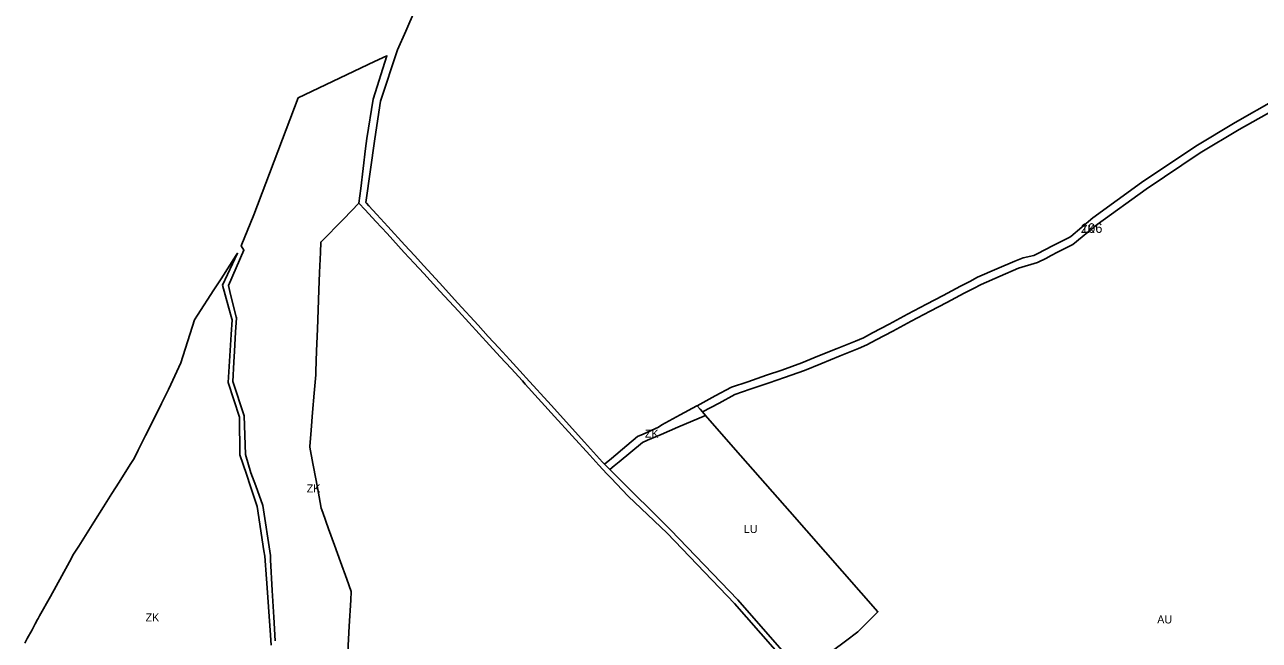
# Model space of a CAD drawing. Extents: x -537068 to -534056, y -1176840 to -1172401.
# Drawn here: x -536897 to -536126, y -1173545 to -1173160 of the extents above; entities that cross this region are included whole.
import ezdxf

# ---------------------------------------------------------------- set-up
doc = ezdxf.new("R2010")
doc.units = 0
for name, color, linetype in [('90710013', 7, 'Continuous'), ('90710023', 7, 'Continuous'), ('90750013', 7, 'Continuous'), ('90770013', 7, 'Continuous'), ('ID_navrh', 7, 'Continuous')]:
    doc.layers.add(name, color=color, linetype=linetype)

msp = doc.modelspace()

# ---------------------------------------------------------------- linework, layer by layer
at = {"layer": '90710013'}
for points in [[(-536740.8, -1173544.87), (-536741.62, -1173530.03), (-536742.54, -1173513.34), (-536743.58, -1173494.26), (-536743.73, -1173491.55), (-536748.44, -1173460.44), (-536752.87, -1173448.15), (-536755.82, -1173439.97), (-536759.21, -1173428.41), (-536759.86, -1173410.37), (-536760.07, -1173404.43), (-536767.21, -1173383.01), (-536766.5, -1173370.87), (-536766.1, -1173363.95), (-536765.41, -1173352.16), (-536764.89, -1173343.17), (-536765.07, -1173342.46), (-536766.85, -1173335.32), (-536769.02, -1173326.62), (-536769.92, -1173323), (-536760.29, -1173300.9), (-536761.91, -1173298.23), (-536754.11, -1173278.82), (-536726.26, -1173205.78), (-536678.67, -1173183.17), (-536670.93, -1173179.49), (-536679.48, -1173206.58), (-536683.5, -1173231.19), (-536684.26, -1173237.49), (-536687.27, -1173262.34), (-536688.39, -1173271.56), (-536697.92, -1173281.27), (-536712.23, -1173295.85), (-536712.48, -1173302.36), (-536712.95, -1173314.83), (-536713.37, -1173325.78), (-536713.85, -1173338.23), (-536714.31, -1173350.16), (-536714.83, -1173363.76), (-536715.32, -1173376.77), (-536715.4, -1173378.79), (-536716.34, -1173390.11), (-536717.35, -1173402.33), (-536718.26, -1173413.33), (-536719.1, -1173423.47), (-536719, -1173424.01), (-536717.13, -1173434.13), (-536715.17, -1173444.76), (-536713.3, -1173454.89), (-536712, -1173461.94), (-536710.97, -1173464.79), (-536707.33, -1173474.88), (-536703.66, -1173485.04), (-536699.85, -1173495.61), (-536695.94, -1173506.43), (-536693.21, -1173513.98), (-536693.52, -1173519.44), (-536694.43, -1173535.65), (-536695.35, -1173551.97)], [(-536897.15, -1173546.32), (-536895.96, -1173544.15), (-536895.72, -1173543.73), (-536895.52, -1173543.35), (-536892.58, -1173538.02), (-536890.52, -1173534.27), (-536889.05, -1173531.62), (-536888.66, -1173530.9), (-536887.8, -1173529.34), (-536881.06, -1173517.1), (-536873.99, -1173504.27), (-536869.22, -1173495.62), (-536866.57, -1173490.8), (-536863.34, -1173485.69), (-536859.16, -1173479.05), (-536853.98, -1173470.84), (-536847.94, -1173461.26), (-536842.65, -1173452.86), (-536838.18, -1173445.78), (-536832.27, -1173436.41), (-536830.84, -1173434.15), (-536828.87, -1173431.02), (-536826.22, -1173425.75), (-536821.63, -1173416.6), (-536816.78, -1173406.94), (-536811.63, -1173396.67), (-536807.24, -1173387.92), (-536805.86, -1173384.88), (-536799.66, -1173371.28), (-536791.11, -1173344.5), (-536789.23, -1173341.58), (-536778.96, -1173325.66), (-536774.53, -1173318.78), (-536765.04, -1173304.06), (-536764.23, -1173302.81), (-536773.59, -1173322.71), (-536771.89, -1173328.86), (-536769.61, -1173337.09), (-536767.72, -1173343.88), (-536767.58, -1173344.39), (-536768.19, -1173353.64), (-536768.85, -1173363.54), (-536770.17, -1173383.46), (-536762.97, -1173405.24), (-536762.75, -1173428.76), (-536758.67, -1173440.8), (-536756.08, -1173448.57), (-536755.51, -1173450.29), (-536751.91, -1173461.06), (-536747.73, -1173488.68), (-536747.24, -1173491.91), (-536746.21, -1173506.04), (-536744.94, -1173523.42), (-536744.91, -1173523.88), (-536743.87, -1173538.18), (-536743.18, -1173547.58)]]:
    msp.add_lwpolyline(points, dxfattribs=at)
msp.add_lwpolyline([(-536531.67, -1173437.87), (-536535.02, -1173434.53), (-536530.74, -1173430.93), (-536521.07, -1173422.8), (-536514.36, -1173417.16), (-536511, -1173415.71), (-536501.3, -1173411.52), (-536499.14, -1173410.01), (-536487.8, -1173403.75), (-536477.34, -1173398.13), (-536477.22, -1173398.07), (-536475.27, -1173400.29), (-536473.84, -1173401.92), (-536471.93, -1173404.1), (-536489.19, -1173411.48), (-536499.62, -1173415.94), (-536508.14, -1173419.59), (-536511.38, -1173420.98), (-536525.93, -1173433.09), (-536528.92, -1173435.58)], close=True, dxfattribs=at)
at = {"layer": '90710023'}
msp.add_lwpolyline([(-536113.11, -1173211.09), (-536138.71, -1173225.54), (-536163.03, -1173240.21), (-536196.76, -1173262.83), (-536227.35, -1173284.86), (-536242.63, -1173297.35), (-536251.72, -1173302.02), (-536256.57, -1173304.51), (-536259.11, -1173305.81), (-536264.58, -1173308.62), (-536276.53, -1173312.23), (-536287.98, -1173317.17), (-536299.84, -1173322.28), (-536304.64, -1173324.81), (-536310.37, -1173327.83), (-536315.87, -1173330.73), (-536321.29, -1173333.59), (-536331.65, -1173339.06), (-536343.44, -1173345.34), (-536355.02, -1173351.51), (-536365.31, -1173356.99), (-536371.16, -1173360.1), (-536376.47, -1173362.27), (-536387.87, -1173366.92), (-536399.85, -1173371.81), (-536410.04, -1173375.97), (-536422.65, -1173380.48), (-536432.27, -1173383.77), (-536443.98, -1173387.77), (-536453.72, -1173391.1), (-536463.51, -1173396.36), (-536473.84, -1173401.92), (-536475.27, -1173400.29), (-536477.22, -1173398.07), (-536465.88, -1173391.96), (-536455.73, -1173386.5), (-536445.6, -1173383.04), (-536433.89, -1173379.04), (-536424.3, -1173375.76), (-536411.83, -1173371.3), (-536401.74, -1173367.18), (-536389.76, -1173362.29), (-536378.36, -1173357.64), (-536373.28, -1173355.57), (-536367.66, -1173352.58), (-536357.37, -1173347.1), (-536345.79, -1173340.93), (-536333.99, -1173334.64), (-536323.62, -1173329.17), (-536318.2, -1173326.31), (-536312.7, -1173323.41), (-536306.97, -1173320.39), (-536302, -1173317.77), (-536289.96, -1173312.58), (-536278.74, -1173307.74), (-536273.57, -1173305.71), (-536266.86, -1173304.17), (-536263.18, -1173302.28), (-536261.39, -1173301.36), (-536258.85, -1173300.06), (-536256.07, -1173298.63), (-536254, -1173297.57), (-536244.91, -1173292.9), (-536243.78, -1173292.32), (-536230.04, -1173280.63), (-536199.61, -1173258.72), (-536165.72, -1173235.99), (-536141.23, -1173221.22), (-536115.5, -1173206.7)], dxfattribs=at)
at = {"layer": '90750013'}
for points in [[(-536115.5, -1173206.7), (-536141.23, -1173221.22), (-536165.72, -1173235.99), (-536199.61, -1173258.72), (-536230.04, -1173280.63), (-536243.78, -1173292.32), (-536244.91, -1173292.9), (-536254, -1173297.57), (-536256.07, -1173298.63), (-536258.85, -1173300.06), (-536261.39, -1173301.36), (-536263.18, -1173302.28), (-536266.86, -1173304.17), (-536273.57, -1173305.71), (-536278.74, -1173307.74), (-536289.96, -1173312.58), (-536302, -1173317.77), (-536306.97, -1173320.39), (-536312.7, -1173323.41), (-536318.2, -1173326.31), (-536323.62, -1173329.17), (-536333.99, -1173334.64), (-536345.79, -1173340.93), (-536357.37, -1173347.1), (-536367.66, -1173352.58), (-536373.28, -1173355.57), (-536378.36, -1173357.64), (-536389.76, -1173362.29), (-536401.74, -1173367.18), (-536411.83, -1173371.3), (-536424.3, -1173375.76), (-536433.89, -1173379.04), (-536445.6, -1173383.04), (-536455.73, -1173386.5), (-536465.88, -1173391.96), (-536477.22, -1173398.07), (-536477.34, -1173398.13), (-536487.8, -1173403.75), (-536499.14, -1173410.01), (-536501.3, -1173411.52), (-536511, -1173415.71), (-536514.36, -1173417.16), (-536521.07, -1173422.8), (-536530.74, -1173430.93), (-536535.02, -1173434.53), (-536536.29, -1173433.26), (-536547.63, -1173420.74), (-536568.41, -1173397.79), (-536584.04, -1173380.53), (-536585.84, -1173378.56), (-536594.23, -1173369.39), (-536600.99, -1173361.99), (-536607.64, -1173354.72), (-536614, -1173347.76), (-536626.56, -1173334.03), (-536638.15, -1173321.36), (-536647.89, -1173310.71), (-536653.74, -1173304.32), (-536659.71, -1173297.8), (-536670.35, -1173286.17), (-536677.16, -1173278.73), (-536682.24, -1173273.17), (-536683.71, -1173271.57), (-536684.19, -1173271.04), (-536678.39, -1173231.46), (-536674.84, -1173207.79), (-536664.26, -1173175.78), (-536659.19, -1173164.25), (-536653.2, -1173150.64)], [(-536384.64, -1173545.08), (-536376.87, -1173539.13), (-536376.51, -1173538.77), (-536364.3, -1173526.67), (-536419.21, -1173464.14), (-536453.14, -1173425.5), (-536471.93, -1173404.1), (-536473.84, -1173401.92), (-536463.51, -1173396.36), (-536453.72, -1173391.1), (-536443.98, -1173387.77), (-536432.27, -1173383.77), (-536422.65, -1173380.48), (-536410.04, -1173375.97), (-536399.85, -1173371.81), (-536387.87, -1173366.92), (-536376.47, -1173362.27), (-536371.16, -1173360.1), (-536365.31, -1173356.99), (-536355.02, -1173351.51), (-536343.44, -1173345.34), (-536331.65, -1173339.06), (-536321.29, -1173333.59), (-536315.87, -1173330.73), (-536310.37, -1173327.83), (-536304.64, -1173324.81), (-536299.84, -1173322.28), (-536287.98, -1173317.17), (-536276.53, -1173312.23), (-536264.58, -1173308.62), (-536259.11, -1173305.81), (-536256.57, -1173304.51), (-536251.72, -1173302.02), (-536242.63, -1173297.35), (-536227.35, -1173284.86), (-536196.76, -1173262.83), (-536163.03, -1173240.21), (-536138.71, -1173225.54), (-536113.11, -1173211.09)], [(-536695.35, -1173551.97), (-536694.43, -1173535.65), (-536693.52, -1173519.44), (-536693.21, -1173513.98), (-536695.94, -1173506.43), (-536699.85, -1173495.61), (-536703.66, -1173485.04), (-536707.33, -1173474.88), (-536710.97, -1173464.79), (-536712, -1173461.94), (-536713.3, -1173454.89), (-536715.17, -1173444.76), (-536717.13, -1173434.13), (-536719, -1173424.01), (-536719.1, -1173423.47), (-536718.26, -1173413.33), (-536717.35, -1173402.33), (-536716.34, -1173390.11), (-536715.4, -1173378.79), (-536715.32, -1173376.77), (-536714.83, -1173363.76), (-536714.31, -1173350.16), (-536713.85, -1173338.23), (-536713.37, -1173325.78), (-536712.95, -1173314.83), (-536712.48, -1173302.36), (-536712.23, -1173295.85), (-536697.92, -1173281.27), (-536688.39, -1173271.56), (-536684.49, -1173275.8), (-536677.84, -1173283.03), (-536670.88, -1173290.59), (-536660.09, -1173302.31), (-536653.99, -1173308.94), (-536647.98, -1173315.47), (-536637.89, -1173326.43), (-536626.28, -1173339.05), (-536613.34, -1173353.12), (-536606.82, -1173360.21), (-536600.12, -1173367.49), (-536593.32, -1173374.88), (-536586.28, -1173382.53), (-536584.5, -1173384.5), (-536566.22, -1173404.68), (-536544.29, -1173428.89), (-536538.55, -1173435.23), (-536533.5, -1173440.57), (-536531.07, -1173443.14), (-536520.33, -1173454.48), (-536495.96, -1173477.72), (-536453.82, -1173521.55), (-536413.54, -1173567.56)]]:
    msp.add_lwpolyline(points, dxfattribs=at)
at = {"layer": '90770013'}
msp.add_lwpolyline([(-536531.67, -1173437.87), (-536528.92, -1173435.58), (-536525.93, -1173433.09), (-536511.38, -1173420.98), (-536508.14, -1173419.59), (-536499.62, -1173415.94), (-536489.19, -1173411.48), (-536471.93, -1173404.1), (-536453.14, -1173425.5), (-536419.21, -1173464.14), (-536364.3, -1173526.67), (-536376.51, -1173538.77), (-536376.87, -1173539.13), (-536384.64, -1173545.08), (-536392.57, -1173551.14), (-536401.43, -1173557.92), (-536406.18, -1173561.55), (-536410.01, -1173564.67), (-536411.22, -1173565.66), (-536451.77, -1173519.35), (-536493.93, -1173475.47), (-536528.81, -1173440.72)], close=True, dxfattribs=at)

# ---------------------------------------------------------------- texts
at = {"layer": '90710013'}
for p in [(-536509.84, -1173417.97), (-536821.65, -1173532.74)]:
    msp.add_text('ZK', height=5, rotation=360, dxfattribs=at).set_placement(p)
msp.add_text('ZK', height=5, dxfattribs=at).set_placement((-536721, -1173452.2))
at = {"layer": '90710023'}
msp.add_text('ZK', height=5, rotation=360, dxfattribs=at).set_placement((-536237.47, -1173290.1))
at = {"layer": '90750013'}
msp.add_text('AU', height=5, rotation=0, dxfattribs=at).set_placement((-536189.85, -1173533.99))
at = {"layer": '90770013'}
msp.add_text('LU', height=5, rotation=0, dxfattribs=at).set_placement((-536447.99, -1173477.52))
at = {"layer": 'ID_navrh'}
msp.add_text('106', height=6, rotation=360, dxfattribs=at).set_placement((-536237.47, -1173290.1))

doc.saveas('drawing.dxf')
